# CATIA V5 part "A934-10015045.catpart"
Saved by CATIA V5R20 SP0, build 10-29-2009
Part number: A934-10015045
Source: Unknown
Property "A": "60.000"
Property "ARTICLENO": "A934-10015045"
Property "B": "30.000"
Property "BOMINFO": "A934-10015045"
Property "CODE": "A934-10015045"
Property "L": "150.000"
Property "L1": "127.860"
Property "LINA": "A934-10015045"
Property "NB": "A934-10015045"
Property "NBSYN": "$CODE."
Property "NN": "A934"
Property "NT": "VDI 3357 H-Type Cam Drivers, self-lubricating"
Property "SUPPLIER": "CF"
Property "T": "45.000"
Property "W": "100.000"
Bounding box of the stored display mesh (mm): x 0 to 150, y 0 to 45, z -100 to 0
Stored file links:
  C:\Users\Utente\Desktop\3D files A934\A934-10015045.catpart
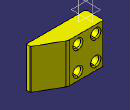
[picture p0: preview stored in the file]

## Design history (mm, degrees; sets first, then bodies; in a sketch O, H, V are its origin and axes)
Body1 "Geometry.1" (main body)
  Solid1 "A934-10015045.catpart": solid without history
